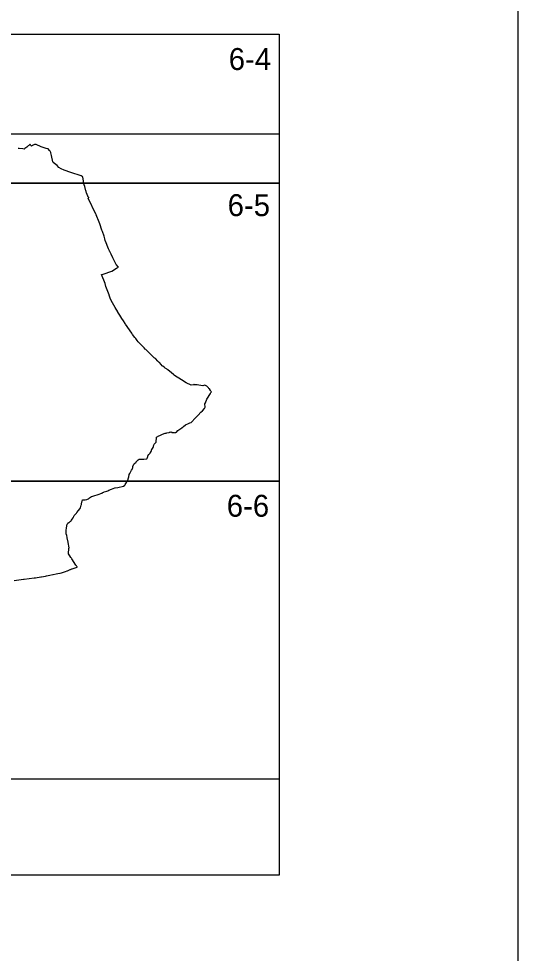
# Model space of a CAD drawing. Extents: x -449577 to -425530, y -1150048 to -1121091.
# Drawn here: x -441514.2 to -441304.5, y -1126663.9 to -1126271.9 of the extents above; entities that cross this region are included whole.
import ezdxf

# ---------------------------------------------------------------- set-up
doc = ezdxf.new("R2010")
doc.units = 0
for name, color, linetype in [('Vrstva 1', 7, 'Continuous'), ('Vrstva 10', 7, 'Continuous'), ('Vrstva 4', 7, 'Continuous')]:
    doc.layers.add(name, color=color, linetype=linetype)

msp = doc.modelspace()

# ---------------------------------------------------------------- linework, layer by layer
at = {"layer": 'Vrstva 1'}
msp.add_lwpolyline([(-442789.49, -1126016.81), (-442789.49, -1127066.81), (-441304.49, -1127066.81), (-441304.49, -1126016.81)], close=True, dxfattribs=at)
msp.add_lwpolyline([(-441516.03, -1126507.56), (-441512.16, -1126506.99), (-441511.92, -1126506.96), (-441507.62, -1126506.44), (-441507.09, -1126506.38), (-441504.94, -1126506.02), (-441504.62, -1126505.97), (-441502.96, -1126505.7), (-441502.56, -1126505.63), (-441501.15, -1126505.34), (-441499.86, -1126505.07), (-441499.65, -1126505.03), (-441498.48, -1126504.8), (-441497.81, -1126504.67), (-441497.79, -1126504.67), (-441496.88, -1126504.46), (-441496.81, -1126504.44), (-441496.16, -1126504.28), (-441495.81, -1126504.17), (-441494.92, -1126503.88), (-441494.48, -1126503.73), (-441493.83, -1126503.49), (-441493.71, -1126503.45), (-441492.62, -1126502.96), (-441492.62, -1126502.96), (-441492.5, -1126502.92), (-441491.85, -1126502.69), (-441491.76, -1126502.66), (-441491.33, -1126502.5), (-441489.67, -1126501.92), (-441489.69, -1126501.87), (-441489.8, -1126501.7), (-441489.96, -1126501.47), (-441490.18, -1126501.15), (-441491.88, -1126498.51), (-441492.09, -1126498.16), (-441492.26, -1126497.89), (-441492.7, -1126497.18), (-441493.23, -1126496.33), (-441493.07, -1126493.97), (-441493.06, -1126493.88), (-441493.45, -1126491.58), (-441493.45, -1126491.56), (-441493.46, -1126491.54), (-441493.46, -1126491.54), (-441493.46, -1126491.51), (-441493.87, -1126489.68), (-441493.88, -1126489.49), (-441493.94, -1126488.69), (-441494.04, -1126488.41), (-441494.05, -1126488.39), (-441494.16, -1126488.17), (-441494.2, -1126488.09), (-441494.21, -1126487.71), (-441494.24, -1126487.01), (-441494.19, -1126486.52), (-441494.19, -1126486.5), (-441494.1, -1126485.64), (-441494.08, -1126485.53), (-441493.79, -1126483.89), (-441493.71, -1126483.81), (-441493.41, -1126483.47), (-441493.35, -1126483.4), (-441493.09, -1126483.28), (-441493.03, -1126483.22), (-441492.77, -1126483.02), (-441492.54, -1126482.84), (-441492.33, -1126482.68), (-441492.27, -1126482.64), (-441492.19, -1126482.51), (-441492.11, -1126482.39), (-441492, -1126482.22), (-441491.78, -1126481.89), (-441491.36, -1126481.24), (-441491.23, -1126480.99), (-441491.22, -1126480.98), (-441491.08, -1126480.69), (-441491.03, -1126480.6), (-441490.85, -1126480.27), (-441490.71, -1126480.12), (-441490.41, -1126479.81), (-441490.24, -1126479.63), (-441489.96, -1126479.28), (-441489.83, -1126479.11), (-441489.14, -1126478.26), (-441488.48, -1126477.45), (-441488.19, -1126477.09), (-441487.95, -1126475.92), (-441487.89, -1126475.69), (-441487.82, -1126475.41), (-441487.5, -1126474.1), (-441487.42, -1126473.82), (-441487.42, -1126473.79), (-441487.4, -1126473.74), (-441487.24, -1126473.73), (-441487.22, -1126473.73), (-441486.98, -1126473.73), (-441486.29, -1126473.71), (-441486.28, -1126473.71), (-441486.25, -1126473.71), (-441485.57, -1126473.53), (-441485.37, -1126473.47), (-441484.95, -1126473.36), (-441484.93, -1126473.35), (-441484.87, -1126473.29), (-441484.57, -1126473.01), (-441484.45, -1126472.93), (-441484.11, -1126472.67), (-441483.69, -1126472.35), (-441483.62, -1126472.33), (-441483.06, -1126472.17), (-441480.36, -1126471.41), (-441479.77, -1126471.14), (-441479.44, -1126470.98), (-441479.39, -1126470.96), (-441479.29, -1126470.91), (-441478.93, -1126470.73), (-441478.88, -1126470.71), (-441478.85, -1126470.69), (-441478.84, -1126470.69), (-441478.81, -1126470.67), (-441478.5, -1126470.52), (-441478.44, -1126470.48), (-441478.33, -1126470.43), (-441477.25, -1126470.1), (-441476.82, -1126469.92), (-441476.3, -1126469.7), (-441475.29, -1126469.29), (-441473.87, -1126468.66), (-441473.73, -1126468.65), (-441472.6, -1126468.6), (-441470.2, -1126468.04), (-441469.67, -1126467.64), (-441469.6, -1126467.52), (-441469.51, -1126467.34), (-441469.25, -1126466.83), (-441468.9, -1126466.4), (-441468.88, -1126466.37), (-441468.67, -1126466.08), (-441468.56, -1126465.92), (-441468.55, -1126465.91), (-441468.01, -1126464.13), (-441468, -1126464.1), (-441467.8, -1126463.15), (-441467.54, -1126462.69), (-441467.35, -1126462.36), (-441466.8, -1126461.24), (-441466.42, -1126460.73), (-441466.39, -1126460.6), (-441466.32, -1126460.3), (-441466.29, -1126460.16), (-441466.23, -1126459.91), (-441466.21, -1126459.81), (-441465.89, -1126458.8), (-441465.88, -1126458.79), (-441465.59, -1126458.51), (-441464.93, -1126457.88), (-441464.88, -1126457.83), (-441464.41, -1126457.35), (-441464.15, -1126457.09), (-441464.05, -1126456.98), (-441463.68, -1126456.66), (-441463.64, -1126456.66), (-441463.63, -1126456.66), (-441463.22, -1126456.65), (-441463.05, -1126456.66), (-441462.42, -1126456.68), (-441461.71, -1126456.68), (-441460.74, -1126456.59), (-441460.71, -1126456.59), (-441460.46, -1126456.56), (-441460.24, -1126456.2), (-441460.19, -1126456.07), (-441460.17, -1126456.02), (-441460.15, -1126455.96), (-441459.79, -1126454.94), (-441459.65, -1126454.77), (-441459.55, -1126454.66), (-441459.51, -1126454.62), (-441459.45, -1126454.54), (-441459.33, -1126454.41), (-441459.06, -1126454.09), (-441458.97, -1126453.99), (-441458.87, -1126453.87), (-441458.53, -1126453.48), (-441458.46, -1126453.09), (-441458.4, -1126452.78), (-441458.33, -1126452.65), (-441457.78, -1126451.73), (-441457.67, -1126451.34), (-441457.48, -1126450.64), (-441457.36, -1126450.35), (-441457.07, -1126450.08), (-441456.52, -1126449.57), (-441456.45, -1126449.51), (-441456.35, -1126447.4), (-441455.33, -1126446.91), (-441454.93, -1126446.7), (-441454.68, -1126446.57), (-441454.39, -1126446.41), (-441454.17, -1126446.33), (-441453.83, -1126446.2), (-441453.78, -1126446.19), (-441452.69, -1126445.78), (-441452.68, -1126445.78), (-441452.19, -1126445.72), (-441452.11, -1126445.7), (-441451.08, -1126445.44), (-441450.93, -1126445.4), (-441450.84, -1126445.37), (-441450.67, -1126445.32), (-441450.14, -1126445.15), (-441450.14, -1126445.15), (-441450.13, -1126445.16), (-441450.13, -1126445.16), (-441450.1, -1126445.22), (-441449.97, -1126445.44), (-441449.09, -1126445.54), (-441448.89, -1126445.56), (-441448.53, -1126445.6), (-441448.44, -1126445.56), (-441448.01, -1126445.38), (-441447.36, -1126444.67), (-441445.72, -1126443.51), (-441445.63, -1126443.44), (-441445.46, -1126443.33), (-441444.95, -1126442.91), (-441444.2, -1126442.31), (-441442.93, -1126441.74), (-441442.31, -1126441.47), (-441441.77, -1126441.23), (-441441.71, -1126441.2), (-441440.06, -1126439.53), (-441439.22, -1126438.64), (-441438.86, -1126438.26), (-441437.67, -1126436.9), (-441437.07, -1126436.44), (-441437.02, -1126436.4), (-441436.18, -1126435.39), (-441435.98, -1126434.82), (-441436.07, -1126433.49), (-441435.85, -1126433), (-441435.21, -1126431.55), (-441433.75, -1126429.07), (-441433.72, -1126429.02), (-441433.72, -1126429.02), (-441433.7, -1126428.99), (-441433.67, -1126428.95), (-441433.52, -1126428.76), (-441433.26, -1126428.42), (-441433.52, -1126428.12), (-441433.66, -1126427.9), (-441434.13, -1126427.16), (-441434.33, -1126426.97), (-441434.48, -1126426.81), (-441434.67, -1126426.61), (-441435.25, -1126426.04), (-441436.1, -1126425.57), (-441436.55, -1126425.75), (-441436.88, -1126425.87), (-441438.63, -1126425.6), (-441439.24, -1126425.51), (-441439.38, -1126425.5), (-441439.97, -1126425.48), (-441440.35, -1126425.43), (-441440.51, -1126425.4), (-441440.55, -1126425.4), (-441440.58, -1126425.39), (-441440.58, -1126425.39), (-441440.61, -1126425.4), (-441440.71, -1126425.43), (-441440.84, -1126425.46), (-441441.74, -1126425.7), (-441441.81, -1126425.67), (-441443.88, -1126424.63), (-441445.9, -1126423.35), (-441448.81, -1126421.53), (-441448.97, -1126421.39), (-441449.01, -1126421.36), (-441449.1, -1126421.28), (-441450.24, -1126420.35), (-441451.39, -1126419.3), (-441451.5, -1126419.2), (-441452.71, -1126418.44), (-441452.99, -1126418.21), (-441453.62, -1126417.71), (-441453.93, -1126417.47), (-441454.43, -1126416.94), (-441455.15, -1126416.18), (-441455.3, -1126416.02), (-441455.76, -1126415.53), (-441456.73, -1126414.5), (-441456.93, -1126414.39), (-441456.93, -1126414.39), (-441457.11, -1126414.3), (-441457.31, -1126414.2), (-441458.14, -1126413.37), (-441458.77, -1126412.74), (-441459.95, -1126411.57), (-441460.88, -1126410.63), (-441461.04, -1126410.48), (-441461.48, -1126410.03), (-441461.72, -1126409.79), (-441461.81, -1126409.7), (-441461.85, -1126409.66), (-441462.37, -1126409.14), (-441463.01, -1126408.49), (-441463.09, -1126408.41), (-441463.11, -1126408.39), (-441463.26, -1126408.24), (-441464.09, -1126407.4), (-441464.47, -1126406.9), (-441464.75, -1126406.53), (-441465.07, -1126406.1), (-441465.43, -1126405.62), (-441466.38, -1126404.36), (-441466.75, -1126403.82), (-441469.29, -1126400.08), (-441469.46, -1126399.82), (-441470.23, -1126398.63), (-441470.9, -1126397.62), (-441471.74, -1126396.29), (-441472.54, -1126395.02), (-441472.62, -1126394.89), (-441473.71, -1126393.04), (-441475.39, -1126390.19), (-441475.39, -1126390.18), (-441475.39, -1126390.18), (-441475.4, -1126390.18), (-441475.73, -1126389.2), (-441476.18, -1126387.9), (-441476.24, -1126387.7), (-441477.62, -1126384.19), (-441477.91, -1126382.94), (-441479.39, -1126379.26), (-441478.76, -1126379.06), (-441475.04, -1126377.82), (-441473.07, -1126376.6), (-441472.89, -1126376.49), (-441472.83, -1126376.45), (-441472.63, -1126376.33), (-441472.36, -1126376.16), (-441473.28, -1126374.97), (-441474.69, -1126372.19), (-441475.44, -1126370.72), (-441475.97, -1126369.56), (-441475.99, -1126369.52), (-441476.05, -1126369.39), (-441476.06, -1126369.36), (-441476.08, -1126369.33), (-441476.12, -1126369.24), (-441476.45, -1126368.51), (-441476.77, -1126367.72), (-441477.48, -1126365.95), (-441477.89, -1126364.91), (-441478.04, -1126364.28), (-441478.3, -1126363.15), (-441479.04, -1126361.26), (-441479.24, -1126360.66), (-441480.18, -1126358.03), (-441480.45, -1126357.31), (-441481.64, -1126354.22), (-441481.71, -1126354.04), (-441481.74, -1126353.96), (-441485.09, -1126347.15), (-441484.78, -1126347.01), (-441484.76, -1126347), (-441484.86, -1126346.83), (-441484.94, -1126346.73), (-441485.11, -1126346.5), (-441485.17, -1126346.42), (-441485.78, -1126344.94), (-441485.83, -1126344.65), (-441485.93, -1126344.19), (-441485.94, -1126344.13), (-441486.45, -1126342.29), (-441486.75, -1126341.66), (-441486.76, -1126341.58), (-441486.8, -1126341.22), (-441486.94, -1126340.13), (-441487.22, -1126338.29), (-441487.28, -1126338.27), (-441487.58, -1126338.17), (-441487.96, -1126337.91), (-441487.97, -1126337.91), (-441492.27, -1126336.5), (-441495.06, -1126335.52), (-441496.37, -1126334.9), (-441497.34, -1126334.34), (-441498.06, -1126333.56), (-441499.74, -1126332.29), (-441499.8, -1126331.99), (-441500.38, -1126329.29), (-441500.53, -1126328.75), (-441500.71, -1126328.24), (-441500.76, -1126328.08), (-441501.01, -1126327.56), (-441501.26, -1126327.25), (-441501.84, -1126326.56), (-441502.59, -1126326.35), (-441504.77, -1126325.69), (-441506.86, -1126324.73), (-441507.48, -1126324.73), (-441508.43, -1126325.1), (-441508.56, -1126325.19), (-441508.63, -1126325.24), (-441508.77, -1126325.34), (-441508.81, -1126325.37), (-441508.83, -1126325.35), (-441509.04, -1126325.1), (-441509.29, -1126324.82), (-441509.37, -1126324.72), (-441509.46, -1126324.76), (-441509.97, -1126325.15), (-441510.16, -1126325.3), (-441510.83, -1126325.82), (-441511.58, -1126326.38), (-441511.92, -1126326.6), (-441512.51, -1126326.56), (-441513.99, -1126326.41), (-441514.45, -1126326.32)], dxfattribs=at)
at = {"layer": 'Vrstva 10'}
msp.add_lwpolyline([(-441404.9, -1126320.23), (-441404.9, -1126631.21), (-441737.77, -1126631.21), (-441737.77, -1126465.91), (-441717.4, -1126465.91), (-441717.4, -1126340.91), (-441717.4, -1126320.23), (-441404.9, -1126320.23)], dxfattribs=at)
at = {"layer": 'Vrstva 4'}
msp.add_line((-441717.4, -1126278.41), (-441404.9, -1126278.41), dxfattribs=at)
msp.add_lwpolyline([(-441404.9, -1126278.41), (-441404.9, -1126340.91), (-441561.15, -1126340.91), (-441561.15, -1126278.41)], dxfattribs=at)
for points in [[(-441404.9, -1126340.91), (-441404.9, -1126465.91), (-441561.15, -1126465.91), (-441561.15, -1126340.91)], [(-441404.9, -1126465.91), (-441404.9, -1126590.91), (-441561.15, -1126590.91), (-441561.15, -1126465.91)]]:
    msp.add_lwpolyline(points, close=True, dxfattribs=at)

# ---------------------------------------------------------------- texts
at = {"layer": 'Vrstva 1'}
for s, p in [('6-4', (-441426.03, -1126293.46)), ('6-5', (-441426.48, -1126354.75)), ('6-6', (-441426.85, -1126480.82))]:
    msp.add_text(s, height=9.2, dxfattribs=at).set_placement(p)

doc.saveas('drawing.dxf')
